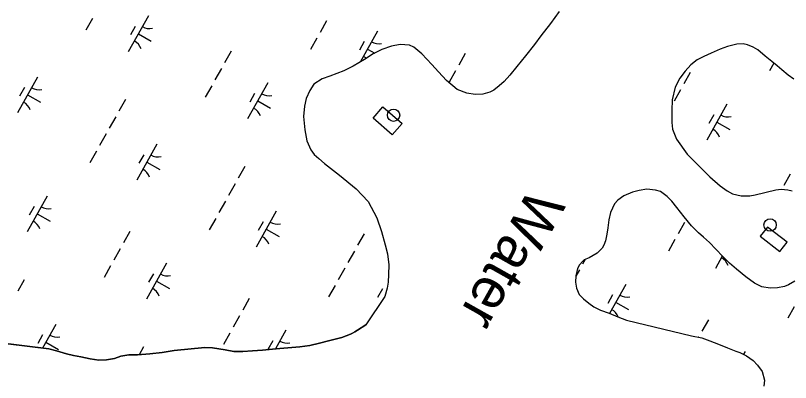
# Model space of a CAD drawing. Extents: x 3913936 to 3933962, y 195330 to 217741.
# Drawn here: x 3920359 to 3921301, y 201515 to 201961 of the extents above; entities that cross this region are included whole.
import ezdxf

# ---------------------------------------------------------------- set-up
doc = ezdxf.new("R2010")
doc.units = 0
for name, color, linetype in [('V-CHAN-DOCK', 7, 'Continuous'), ('V-DOMW-TANK', 7, 'Continuous'), ('V-RIVR-IDEN', 7, 'Continuous'), ('V-TOPO-SHOR', 7, 'Continuous'), ('V-WETL-SWMP', 7, 'Continuous')]:
    doc.layers.add(name, color=color, linetype=linetype)

msp = doc.modelspace()

# ---------------------------------------------------------------- linework, layer by layer
at = {"layer": 'V-CHAN-DOCK'}
for points in [[(3920805.84, 201849.96), (3920829.12, 201829.47), (3920817.07, 201815.79), (3920793.8, 201836.27)], [(3921264.32, 201692.78), (3921288.25, 201674.29), (3921296.88, 201685.47), (3921272.96, 201703.95)]]:
    msp.add_lwpolyline(points, close=True, dxfattribs=at)
at = {"layer": 'V-DOMW-TANK'}
for centre in [(3920818.73, 201839.67), (3921276.3, 201706.44)]:
    msp.add_circle(centre, 7.5, dxfattribs=at)
at = {"layer": 'V-TOPO-SHOR'}
for points in [[(3921019.82, 201965.67), (3921009.31, 201951.23), (3920997.78, 201936.02), (3920989.83, 201925.71), (3920978.81, 201911.78), (3920968.55, 201898.89), (3920959.83, 201888.32), (3920952.91, 201880.84), (3920947, 201875.42), (3920940.59, 201870), (3920935.71, 201867.67), (3920926.97, 201865.33), (3920917.71, 201864.79), (3920907.67, 201866.56), (3920895.82, 201870.9), (3920882.93, 201881.67), (3920873.38, 201892.19), (3920865.38, 201901.17), (3920852.99, 201914.26), (3920843.19, 201922.47), (3920838.04, 201924.77), (3920826.72, 201925.51), (3920816.18, 201923.42), (3920804.35, 201919.53), (3920793.82, 201914.1), (3920783.55, 201907.38), (3920769.42, 201899.11), (3920758.37, 201893.42), (3920741.41, 201887.19), (3920731.9, 201884.08), (3920721.88, 201877.36), (3920717.02, 201869.63), (3920712.67, 201859.84), (3920710.38, 201850.83), (3920709.13, 201838.22), (3920710.72, 201822.02), (3920713.33, 201808.65), (3920718.25, 201797.85), (3920722.38, 201792.21), (3920727.79, 201787.08), (3920734.76, 201780.92), (3920753.07, 201766.82), (3920773.18, 201750.15), (3920787.89, 201734.76), (3920798.23, 201715.23), (3920803.94, 201698.53), (3920808.36, 201682.33), (3920811.48, 201671.53), (3920813.06, 201657.9), (3920812.57, 201646.32), (3920812.09, 201637.06), (3920810.82, 201629.59)], [(3921305.23, 201883.62), (3921298.29, 201888.48), (3921290.56, 201894.88), (3921284.64, 201899.48), (3921278.2, 201904.86), (3921270.22, 201911.52), (3921261.21, 201918.94), (3921255.81, 201922.52), (3921248.86, 201925.33), (3921243.46, 201926.34), (3921235.76, 201925.81), (3921224.46, 201923.21), (3921215.74, 201919.84), (3921204.71, 201915.19), (3921195.73, 201910.8), (3921187.77, 201906.92), (3921179.83, 201900.73), (3921172.91, 201893.01), (3921166.52, 201884.77), (3921160.89, 201873.96), (3921157.08, 201858.54), (3921156.86, 201845.44), (3921156.91, 201830.8), (3921157.44, 201822.58), (3921162.35, 201810.77), (3921175.51, 201792.32), (3921203.07, 201764.91), (3921215.69, 201754.15), (3921223.93, 201747.75), (3921230.61, 201744.18), (3921241.15, 201741.64), (3921251.69, 201741.67), (3921258.1, 201742.97), (3921283.26, 201749.2), (3921289.68, 201749.99), (3921297.65, 201749.24), (3921303.05, 201747.72)], [(3921306.43, 201638.29), (3921298.74, 201633.9), (3921293.61, 201631.58), (3921285.39, 201630.27), (3921276.15, 201629.73), (3921266.12, 201631.5), (3921257.38, 201635.85), (3921246.82, 201643.52), (3921235.23, 201652.99), (3921226.74, 201660.17), (3921218.75, 201668.11), (3921210.25, 201677.07), (3921202.78, 201685.02), (3921195.31, 201691.67), (3921189.13, 201697.05), (3921180.89, 201705.25), (3921171.61, 201716.52), (3921163.1, 201727.55), (3921156.66, 201735.49), (3921151.25, 201741.13), (3921143.01, 201747.01), (3921136.84, 201748.79), (3921126.3, 201749.79), (3921117.06, 201748.48), (3921109.1, 201746.15), (3921098.58, 201741.75), (3921091.15, 201736.59), (3921087.31, 201732.21), (3921082.2, 201721.41), (3921080.17, 201712.67), (3921078.91, 201703.17), (3921077.91, 201695.46), (3921076.13, 201687.23), (3921074.35, 201682.09), (3921072.04, 201678.23), (3921065.9, 201672.05), (3921056.41, 201666.37), (3921050.5, 201664.04), (3921048.71, 201662.49), (3921044.62, 201657.86), (3921042.31, 201653.74), (3921040.28, 201644.74), (3921039.79, 201637.04), (3921040.84, 201629.85), (3921044.2, 201622.15), (3921049.61, 201616.77), (3921056.05, 201611.39), (3921062.22, 201607.04), (3921070.2, 201603.21), (3921080.48, 201599.39), (3921091.03, 201595.05), (3921101.83, 201590.71), (3921180.75, 201571.93), (3921193.08, 201569.39), (3921203.11, 201565.82), (3921213.4, 201561.74), (3921224.46, 201557.15), (3921234.49, 201553.32), (3921239.37, 201551.54), (3921247.6, 201547.71), (3921255.84, 201541.82), (3921260.99, 201536.18), (3921266.41, 201528.49), (3921269.26, 201518.23), (3921268.51, 201510.77)], [(3920810.82, 201629.59), (3920808.28, 201619.55), (3920785.12, 201585.1)], [(3920755.7, 201570.03), (3920766.52, 201573.93), (3920768.67, 201574.96), (3920771.76, 201576.86), (3920775.02, 201578.93), (3920785.12, 201585.1)], [(3920326.89, 201564.96), (3920399.89, 201555.97), (3920409.26, 201553.76), (3920421.14, 201550.01), (3920429.91, 201547.8), (3920438.68, 201546.19), (3920450.2, 201544.08), (3920460.52, 201542.47), (3920470.06, 201542.84), (3920479.69, 201544.42), (3920487.24, 201547.19), (3920497.04, 201548.59), (3920507.35, 201548.79), (3920522.48, 201549.95), (3920537.6, 201551.8), (3920551.95, 201554.07), (3920589.24, 201557.7), (3920598.61, 201557.21), (3920614, 201554.76), (3920624.5, 201552.64), (3920635.41, 201552.67), (3920647.19, 201553.48), (3920659.48, 201554.29), (3920675.54, 201555.96), (3920704.94, 201558.46), (3920717.14, 201560.29), (3920728.65, 201562.82), (3920739.64, 201565.6), (3920749.52, 201568.29), (3920755.7, 201570.03)]]:
    msp.add_lwpolyline(points, dxfattribs=at)
at = {"layer": 'V-WETL-SWMP'}
for p, q in [((3921019.82, 201965.67), (3921009.31, 201951.23)), ((3920452.74, 201957.01), (3920444.9, 201943.06)), ((3920520.83, 201960.37), (3920496.33, 201916.78)), ((3920737.27, 201954.17), (3920729.43, 201940.22)), ((3920504.8, 201947.58), (3920498.92, 201937.12)), ((3921009.31, 201951.23), (3920997.78, 201936.02)), ((3920508.58, 201938.57), (3920524.27, 201929.75)), ((3920725.51, 201933.25), (3920717.67, 201919.3)), ((3920799.2, 201941.82), (3920778.02, 201904.14)), ((3920997.78, 201936.02), (3920989.83, 201925.71)), ((3920783.16, 201929.03), (3920777.28, 201918.57)), ((3920816.18, 201923.42), (3920804.35, 201919.53)), ((3920826.72, 201925.51), (3920816.18, 201923.42)), ((3920838.04, 201924.77), (3920826.72, 201925.51)), ((3920843.19, 201922.47), (3920838.04, 201924.77)), ((3920989.83, 201925.71), (3920978.81, 201911.78)), ((3921235.76, 201925.81), (3921224.46, 201923.21)), ((3921243.46, 201926.34), (3921235.76, 201925.81)), ((3921248.86, 201925.33), (3921243.46, 201926.34)), ((3921255.81, 201922.52), (3921248.86, 201925.33)), ((3920621.26, 201917.34), (3920613.41, 201903.39)), ((3920793.82, 201914.1), (3920783.55, 201907.38)), ((3920786.95, 201920.02), (3920795.74, 201915.08)), ((3920804.35, 201919.53), (3920793.82, 201914.1)), ((3920852.99, 201914.26), (3920843.19, 201922.47)), ((3920865.38, 201901.17), (3920852.99, 201914.26)), ((3920905.79, 201914.5), (3920897.95, 201900.55)), ((3921204.71, 201915.19), (3921195.73, 201910.8)), ((3921215.74, 201919.84), (3921204.71, 201915.19)), ((3921224.46, 201923.21), (3921215.74, 201919.84)), ((3921261.21, 201918.94), (3921255.81, 201922.52)), ((3921270.22, 201911.52), (3921261.21, 201918.94)), ((3920783.55, 201907.38), (3920769.42, 201899.11)), ((3920978.81, 201911.78), (3920968.55, 201898.89)), ((3921187.77, 201906.92), (3921179.83, 201900.73)), ((3921195.73, 201910.8), (3921187.77, 201906.92)), ((3921278.2, 201904.86), (3921270.22, 201911.52)), ((3921284.64, 201899.48), (3921278.2, 201904.86)), ((3920609.49, 201896.42), (3920601.65, 201882.47)), ((3920769.42, 201899.11), (3920758.37, 201893.42)), ((3920873.38, 201892.19), (3920865.38, 201901.17)), ((3920968.55, 201898.89), (3920959.83, 201888.32)), ((3921179.83, 201900.73), (3921172.91, 201893.01)), ((3921280.79, 201902.7), (3921275.64, 201893.53)), ((3921290.56, 201894.88), (3921284.64, 201899.48)), ((3920386.23, 201886.08), (3920361.73, 201842.49)), ((3920741.41, 201887.19), (3920731.9, 201884.08)), ((3920758.37, 201893.42), (3920741.41, 201887.19)), ((3920882.93, 201881.67), (3920873.38, 201892.19)), ((3920894.03, 201893.58), (3920886.19, 201879.63)), ((3920959.83, 201888.32), (3920952.91, 201880.84)), ((3921172.91, 201893.01), (3921166.52, 201884.77)), ((3921179.22, 201891.57), (3921171.38, 201877.63)), ((3921298.29, 201888.48), (3921290.56, 201894.88)), ((3921305.23, 201883.61), (3921298.29, 201888.48)), ((3920665.83, 201878.86), (3920641.33, 201835.27)), ((3920721.88, 201877.36), (3920717.02, 201869.63)), ((3920731.9, 201884.08), (3920721.88, 201877.36)), ((3920895.82, 201870.9), (3920882.93, 201881.67)), ((3920952.91, 201880.84), (3920947.01, 201875.42)), ((3921166.52, 201884.77), (3921160.89, 201873.96)), ((3920370.19, 201873.29), (3920364.31, 201862.83)), ((3920597.73, 201875.5), (3920589.89, 201861.55)), ((3920717.02, 201869.63), (3920712.67, 201859.84)), ((3920907.67, 201866.56), (3920895.82, 201870.9)), ((3920935.71, 201867.67), (3920926.97, 201865.33)), ((3920940.59, 201870), (3920935.71, 201867.67)), ((3920947.01, 201875.42), (3920940.59, 201870)), ((3921160.89, 201873.96), (3921157.08, 201858.54)), ((3921167.46, 201870.65), (3921159.62, 201856.7)), ((3920373.98, 201864.28), (3920389.67, 201855.46)), ((3920492.82, 201858.76), (3920484.98, 201844.81)), ((3920649.8, 201866.08), (3920643.92, 201855.61)), ((3920712.67, 201859.84), (3920710.38, 201850.83)), ((3920917.71, 201864.79), (3920907.67, 201866.56)), ((3920926.97, 201865.33), (3920917.71, 201864.79)), ((3921157.08, 201858.54), (3921156.86, 201845.44)), ((3920653.58, 201857.06), (3920669.27, 201848.24)), ((3920710.38, 201850.83), (3920709.13, 201838.22)), ((3921223.8, 201853.09), (3921199.3, 201809.5)), ((3921156.86, 201845.44), (3921156.9, 201830.8)), ((3921207.76, 201840.31), (3921201.88, 201829.85)), ((3920481.06, 201837.84), (3920473.22, 201823.89)), ((3920709.13, 201838.22), (3920710.72, 201822.02)), ((3921156.9, 201830.8), (3921157.44, 201822.58)), ((3921211.55, 201831.3), (3921227.24, 201822.48)), ((3920710.72, 201822.02), (3920713.33, 201808.65)), ((3921157.44, 201822.58), (3921162.35, 201810.77)), ((3920469.3, 201816.92), (3920461.46, 201802.97)), ((3921162.35, 201810.77), (3921175.51, 201792.32)), ((3920531.23, 201804.57), (3920506.73, 201760.98)), ((3920713.33, 201808.65), (3920718.25, 201797.85)), ((3920457.54, 201796), (3920449.7, 201782.05)), ((3920515.19, 201791.79), (3920509.31, 201781.32)), ((3920718.25, 201797.85), (3920722.38, 201792.21)), ((3920722.38, 201792.21), (3920727.79, 201787.08)), ((3921175.51, 201792.32), (3921203.07, 201764.91)), ((3920518.98, 201782.77), (3920534.67, 201773.95)), ((3920727.79, 201787.08), (3920734.76, 201780.92)), ((3920637.82, 201777.25), (3920629.98, 201763.3)), ((3920734.76, 201780.92), (3920753.06, 201766.82)), ((3920735.2, 201780.58), (3920734.89, 201780.04)), ((3920753.06, 201766.82), (3920773.18, 201750.15)), ((3921203.07, 201764.91), (3921215.69, 201754.15)), ((3921300.7, 201768.22), (3921292.86, 201754.27)), ((3920626.06, 201756.33), (3920618.22, 201742.38)), ((3921215.69, 201754.15), (3921223.93, 201747.75)), ((3920773.18, 201750.15), (3920787.89, 201734.76)), ((3921109.1, 201746.15), (3921098.58, 201741.75)), ((3921117.06, 201748.48), (3921109.1, 201746.15)), ((3921126.3, 201749.79), (3921117.06, 201748.48)), ((3921136.84, 201748.8), (3921126.3, 201749.79)), ((3921143.01, 201747.01), (3921136.84, 201748.8)), ((3921151.25, 201741.13), (3921143.01, 201747.01)), ((3921223.93, 201747.75), (3921230.61, 201744.18)), ((3921258.1, 201742.97), (3921283.26, 201749.2)), ((3921283.26, 201749.2), (3921289.68, 201749.99)), ((3921289.68, 201749.99), (3921297.65, 201749.24)), ((3921297.65, 201749.24), (3921303.04, 201747.72)), ((3920397.86, 201741.61), (3920373.36, 201698.02)), ((3920614.3, 201735.41), (3920606.46, 201721.46)), ((3921091.15, 201736.59), (3921087.31, 201732.22)), ((3921098.58, 201741.75), (3921091.15, 201736.59)), ((3921156.66, 201735.49), (3921151.25, 201741.13)), ((3921163.1, 201727.55), (3921156.66, 201735.49)), ((3921230.61, 201744.18), (3921241.15, 201741.64)), ((3921241.15, 201741.64), (3921251.69, 201741.67)), ((3921251.69, 201741.67), (3921258.1, 201742.97)), ((3920381.82, 201728.83), (3920375.94, 201718.37)), ((3920787.89, 201734.76), (3920798.23, 201715.23)), ((3921087.31, 201732.22), (3921082.2, 201721.41)), ((3921171.61, 201716.52), (3921163.1, 201727.55)), ((3920385.61, 201719.81), (3920401.3, 201710.99)), ((3920676.23, 201723.06), (3920651.73, 201679.47)), ((3921082.2, 201721.41), (3921080.17, 201712.67)), ((3921180.89, 201705.25), (3921171.61, 201716.52)), ((3920602.54, 201714.49), (3920594.7, 201700.54)), ((3920660.19, 201710.28), (3920654.31, 201699.82)), ((3920798.23, 201715.23), (3920803.94, 201698.53)), ((3921080.17, 201712.67), (3921078.91, 201703.17)), ((3921172.27, 201709.64), (3921164.43, 201695.69)), ((3920498.28, 201698.58), (3920490.44, 201684.64)), ((3920663.98, 201701.26), (3920679.67, 201692.44)), ((3920803.94, 201698.53), (3920808.36, 201682.33)), ((3921078.91, 201703.17), (3921077.9, 201695.46)), ((3921189.13, 201697.05), (3921180.89, 201705.25)), ((3920782.82, 201695.74), (3920774.98, 201681.8)), ((3921077.9, 201695.46), (3921076.13, 201687.23)), ((3921160.51, 201688.72), (3921152.67, 201674.77)), ((3921195.31, 201691.67), (3921189.13, 201697.05)), ((3921202.78, 201685.02), (3921195.31, 201691.67)), ((3920808.36, 201682.33), (3920811.48, 201671.53)), ((3921074.35, 201682.09), (3921072.04, 201678.23)), ((3921076.13, 201687.23), (3921074.35, 201682.09)), ((3921210.25, 201677.07), (3921202.78, 201685.02)), ((3920486.52, 201677.66), (3920478.68, 201663.71)), ((3920771.06, 201674.82), (3920763.22, 201660.87)), ((3920811.48, 201671.53), (3920813.06, 201657.9)), ((3921065.9, 201672.05), (3921056.41, 201666.37)), ((3921072.04, 201678.23), (3921065.9, 201672.05)), ((3921218.75, 201668.11), (3921210.25, 201677.07)), ((3921212.59, 201674.6), (3921212.28, 201674.05)), ((3920542.86, 201660.1), (3920518.36, 201616.51)), ((3921048.71, 201662.49), (3921044.61, 201657.86)), ((3921051.55, 201664.45), (3921048.41, 201658.87)), ((3921050.5, 201664.04), (3921048.71, 201662.49)), ((3921056.41, 201666.37), (3921050.5, 201664.04)), ((3921218.15, 201668.74), (3921209.69, 201653.7)), ((3921226.74, 201660.16), (3921218.75, 201668.11)), ((3921235.23, 201652.99), (3921226.74, 201660.16)), ((3920474.76, 201656.74), (3920466.92, 201642.79)), ((3920759.3, 201653.9), (3920751.46, 201639.95)), ((3920813.06, 201657.9), (3920812.57, 201646.32)), ((3921044.49, 201651.89), (3921040.26, 201644.37)), ((3921042.31, 201653.74), (3921040.28, 201644.74)), ((3921044.61, 201657.86), (3921042.31, 201653.74)), ((3921246.82, 201643.52), (3921235.23, 201652.99)), ((3920526.82, 201647.32), (3920520.94, 201636.86)), ((3920812.57, 201646.32), (3920812.09, 201637.06)), ((3921040.28, 201644.74), (3921039.79, 201637.04)), ((3921257.38, 201635.85), (3921246.82, 201643.52)), ((3920369.85, 201640), (3920362.01, 201626.06)), ((3920530.61, 201638.31), (3920546.3, 201629.48)), ((3920747.54, 201632.98), (3920739.7, 201619.03)), ((3920812.09, 201637.06), (3920810.82, 201629.6)), ((3921039.79, 201637.04), (3921040.84, 201629.85)), ((3921100.83, 201634.33), (3921081.05, 201599.15)), ((3921266.12, 201631.5), (3921257.38, 201635.85)), ((3921276.15, 201629.73), (3921266.12, 201631.5)), ((3921293.61, 201631.58), (3921285.39, 201630.27)), ((3921298.74, 201633.9), (3921293.61, 201631.58)), ((3921306.43, 201638.29), (3921298.74, 201633.9)), ((3920805.19, 201628.77), (3920799.31, 201618.31)), ((3920810.82, 201629.6), (3920808.27, 201619.55)), ((3921040.84, 201629.85), (3921044.2, 201622.15)), ((3921044.2, 201622.15), (3921049.61, 201616.77)), ((3921285.39, 201630.27), (3921276.15, 201629.73)), ((3920643.28, 201617.07), (3920635.44, 201603.13)), ((3920808.27, 201619.55), (3920785.13, 201585.1)), ((3921049.61, 201616.77), (3921056.05, 201611.39)), ((3921084.79, 201621.55), (3921078.91, 201611.09)), ((3921088.57, 201612.54), (3921104.27, 201603.72)), ((3921056.05, 201611.39), (3921062.22, 201607.04)), ((3921062.22, 201607.04), (3921070.2, 201603.21)), ((3921070.2, 201603.21), (3921080.48, 201599.39)), ((3921305.5, 201607.21), (3921297.66, 201593.26)), ((3920631.52, 201596.15), (3920623.68, 201582.21)), ((3921080.48, 201599.39), (3921091.03, 201595.05)), ((3921091.03, 201595.05), (3921101.83, 201590.71)), ((3920408.26, 201585.81), (3920392.03, 201556.94)), ((3920785.13, 201585.1), (3920775.02, 201578.93)), ((3921101.83, 201590.71), (3921180.75, 201571.92)), ((3921201.25, 201591.3), (3921193.41, 201577.36)), ((3920619.76, 201575.23), (3920611.92, 201561.28)), ((3920687.86, 201578.59), (3920675.11, 201555.92)), ((3920768.67, 201574.96), (3920766.52, 201573.93)), ((3920771.76, 201576.86), (3920768.67, 201574.96)), ((3920775.02, 201578.93), (3920771.76, 201576.86)), ((3920392.22, 201573.03), (3920386.34, 201562.57)), ((3920671.82, 201565.81), (3920665.94, 201555.35)), ((3920739.64, 201565.6), (3920728.65, 201562.82)), ((3920749.52, 201568.29), (3920739.64, 201565.6)), ((3920755.7, 201570.03), (3920749.52, 201568.29)), ((3920766.52, 201573.93), (3920755.7, 201570.03)), ((3921180.75, 201571.92), (3921193.08, 201569.39)), ((3921189.49, 201570.38), (3921189.36, 201570.15)), ((3921193.08, 201569.39), (3921203.11, 201565.82)), ((3921203.11, 201565.82), (3921213.4, 201561.74)), ((3920399.89, 201555.97), (3920326.89, 201564.96)), ((3920396, 201564.02), (3920411.7, 201555.19)), ((3920409.26, 201553.76), (3920399.89, 201555.97)), ((3920514.85, 201558.49), (3920509.49, 201548.96)), ((3920589.24, 201557.7), (3920551.95, 201554.07)), ((3920598.61, 201557.21), (3920589.24, 201557.7)), ((3920614, 201554.76), (3920598.61, 201557.21)), ((3920675.54, 201555.96), (3920659.48, 201554.29)), ((3920704.94, 201558.45), (3920675.54, 201555.96)), ((3920675.61, 201556.8), (3920676.88, 201556.08)), ((3920717.14, 201560.29), (3920704.94, 201558.45)), ((3920728.65, 201562.82), (3920717.14, 201560.29)), ((3921213.4, 201561.74), (3921224.46, 201557.15)), ((3921224.46, 201557.15), (3921234.49, 201553.32)), ((3920421.14, 201550.01), (3920409.26, 201553.76)), ((3920429.91, 201547.8), (3920421.14, 201550.01)), ((3920438.68, 201546.19), (3920429.91, 201547.8)), ((3920487.24, 201547.19), (3920479.69, 201544.42)), ((3920497.04, 201548.59), (3920487.24, 201547.19)), ((3920507.35, 201548.79), (3920497.04, 201548.59)), ((3920522.48, 201549.95), (3920507.35, 201548.79)), ((3920537.6, 201551.8), (3920522.48, 201549.95)), ((3920551.95, 201554.07), (3920537.6, 201551.8)), ((3920624.5, 201552.64), (3920614, 201554.76)), ((3920635.41, 201552.67), (3920624.5, 201552.64)), ((3920647.19, 201553.48), (3920635.41, 201552.67)), ((3920659.48, 201554.29), (3920647.19, 201553.48)), ((3921234.49, 201553.32), (3921239.37, 201551.54)), ((3921239.37, 201551.54), (3921247.6, 201547.71)), ((3921245.82, 201552.82), (3921243.91, 201549.42)), ((3921247.6, 201547.71), (3921255.84, 201541.82)), ((3920450.2, 201544.08), (3920438.68, 201546.19)), ((3920460.52, 201542.47), (3920450.2, 201544.08)), ((3920470.06, 201542.84), (3920460.52, 201542.47)), ((3920479.69, 201544.42), (3920470.06, 201542.84)), ((3921255.84, 201541.82), (3921260.99, 201536.18)), ((3921260.99, 201536.18), (3921266.41, 201528.49)), ((3921266.41, 201528.49), (3921269.26, 201518.23)), ((3921269.26, 201518.23), (3921268.51, 201510.77))]:
    msp.add_line(p, q, dxfattribs=at)
for centre, start, end in [((3920522.33, 201962.54), 239.88608, 281.42974), ((3920495.25, 201914.38), 19.88608, 61.42973), ((3920800.69, 201943.99), 239.88608, 281.42974), ((3920773.62, 201895.83), 47.08322, 61.42973), ((3920387.72, 201888.24), 239.88608, 281.42974), ((3920667.32, 201881.03), 239.88608, 281.42974), ((3920360.65, 201840.09), 19.88608, 61.42973), ((3920640.25, 201832.87), 19.88608, 61.42973), ((3921225.29, 201855.26), 239.88608, 281.42974), ((3921198.22, 201807.1), 19.88608, 61.42973), ((3920532.72, 201806.74), 239.88608, 281.42974), ((3920505.65, 201758.58), 19.88608, 61.42973), ((3920399.35, 201743.78), 239.88608, 281.42974), ((3920372.28, 201695.62), 19.88608, 61.42973), ((3920677.72, 201725.23), 239.88608, 281.42974), ((3920650.65, 201677.07), 19.88608, 61.42973), ((3921208.61, 201651.3), 19.88608, 61.42973), ((3920544.35, 201662.27), 239.88608, 281.42974), ((3920517.28, 201614.11), 19.88608, 61.42973), ((3921102.32, 201636.5), 239.88608, 281.42974), ((3921075.25, 201588.34), 21.5106, 61.42973), ((3920409.75, 201587.98), 239.88608, 281.42974), ((3920689.35, 201580.76), 239.88608, 281.42974)]:
    msp.add_arc(centre, 17.62, start, end, dxfattribs=at)

# ---------------------------------------------------------------- texts
at = {"layer": 'V-RIVR-IDEN'}
msp.add_text('Water', height=50, rotation=240.67305, dxfattribs=at).set_placement((3920984.73, 201753.58))

doc.saveas('drawing.dxf')
